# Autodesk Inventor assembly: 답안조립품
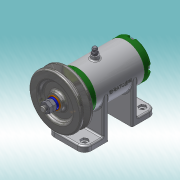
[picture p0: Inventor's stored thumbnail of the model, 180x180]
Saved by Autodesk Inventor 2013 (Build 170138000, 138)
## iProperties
Created: 2017-02
Part Number: 답안조립품
Document SubType Name: Assembly
Designer: dgall
Author: dgall
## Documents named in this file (16)
- C:\Users\dgall\Desktop\470207V1022\답안조립품.iam
- C:\Users\dgall\Desktop\470207V1022\본체.ipt
- C:\Users\dgall\Desktop\470207V1022\V벨트풀리.ipt
- C:\Users\dgall\Desktop\470207V1022\너트 M 8.ipt
- C:\Users\dgall\Desktop\470207V1022\니플 M 6 x 0.75.ipt
- C:\Users\dgall\Desktop\470207V1022\뒤커버.ipt
- C:\Users\dgall\Desktop\470207V1022\베어링 15 x 32 x 9.ipt
- C:\Users\dgall\Desktop\470207V1022\볼트 M 6 x 8.ipt
- C:\Users\dgall\Desktop\470207V1022\볼트 M4 x 12.ipt
- C:\Users\dgall\Desktop\470207V1022\스프링와셔 8.ipt
- C:\Users\dgall\Desktop\470207V1022\앞커버.ipt
- C:\Users\dgall\Desktop\470207V1022\오일 실 15 25 7.ipt
- C:\Users\dgall\Desktop\470207V1022\와셔 6x11.5.ipt
- C:\Users\dgall\Desktop\470207V1022\와셔 8x17.ipt
- C:\Users\dgall\Desktop\470207V1022\축.ipt
- C:\Users\dgall\Desktop\470207V1022\키 3 x 3 x 12.ipt
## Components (11 placed, 3 different names)
1. V벨트풀리:1
2. KS B 2023 6002 - 15 x 32 x 9:1
3. KS B 2023 6002 - 15 x 32 x 9:2
4. ISO 4762 M4 x 12:2
5. ISO 4762 M4 x 12:3
6. ISO 4762 M4 x 12:4
7. ISO 4762 M4 x 12:5
8. ISO 4762 M4 x 12:1
9. ISO 4762 M4 x 12:6
10. ISO 4762 M4 x 12:7
11. ISO 4762 M4 x 12:8
